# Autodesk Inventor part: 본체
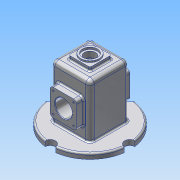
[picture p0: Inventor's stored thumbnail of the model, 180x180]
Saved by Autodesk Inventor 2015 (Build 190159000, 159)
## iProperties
Created: 2018-07
Part Number: 본체
Material: 알루미늄 6061
Document SubType Name: Modeling
Designer: user
Density: 2.7 g/cm^3
Appearance: 알루미늄 - 평지
Author: user
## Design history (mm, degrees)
sketch "스케치1"
  geometry: L1 (-37, -37)-(37, -37); L2 (37, -37)-(37, 37); L3 (37, 37)-(-37, 37); L4 (-37, 37)-(-37, -37); L5 (-37, -37)-(37, 37); L6 (37, -37)-(-37, 37); 1 further point
  constraints: 12 end point, 2 midpoint, 2 parallel, 1 horizontal, 1 perpendicular
  dimensions: "d0" = 74 distance of L3.end L2.end; "d1" = 74 distance of L2.end L1.end
extrude "돌출1" new body sketch "스케치1" stored distance "d2" = 100; taper "d3" = 0 deg
feature "쉘1" dims "d17" = 5
sketch "스케치4"
  geometry: L1 (32, 32)-(32, -32) reference; L2 (32, -32)-(-32, -32) reference; L3 (-32, -32)-(-32, 32) reference; L4 (-32, 32)-(32, 32) reference; C1 r 75 at (0, 0); 1 further point
  constraints: 1 centre point, 1 coincident
  dimensions: "d18" = 150 diameter of C1
extrude "돌출3" join sketch "스케치4" distance "d19" = 10; taper "d20" = 0 deg
sketch "스케치5"
  geometry: L1 (0, 0)-(-75, 0); 1 further point
  constraints: 2 end point, 1 coincident, 1 horizontal, 1 horizontal alignment, 1 other
hole "구멍2" sketch "스케치5" at (-75, 0) diameter "d21" = 20; stored, may be unused: countersink angle "d25" = 90 deg, drill point angle "d27" = 118 deg; dims "d22" = 6, "d23" = 4, "d24" = 2, "d26" = 8
sketch "스케치6"
  geometry: L1 (12, -80)-(62, -80); L2 (62, -80)-(62, -30); L3 (62, -30)-(12, -30); L4 (12, -30)-(12, -80); L5 (12, -80)-(62, -30); L6 (62, -80)-(12, -30); L7 (46.978, -110)-(27.022, -110) reference; 1 further point
  constraints: 12 end point, 2 midpoint, 2 parallel, 1 horizontal, 1 perpendicular
  dimensions: "d31" = 50 distance of L3.end L2.end; "d32" = 50 distance of L2.end L1.end; "d77" = 55 distance from line of L7 point (37, -55)
extrude "돌출4" join sketch "스케치6" distance "d33" = 13; taper "d34" = 0 deg
sketch "스케치9"
  geometry: L1 (-20, -20)-(20, -20); L2 (20, -20)-(20, 20); L3 (20, 20)-(-20, 20); L4 (-20, 20)-(-20, -20); L5 (-20, -20)-(20, 20); L6 (20, -20)-(-20, 20); 1 further point
  constraints: 12 end point, 2 midpoint, 2 parallel, 1 horizontal, 1 perpendicular
  dimensions: "d42" = 40 distance of L3.end L2.end; "d43" = 40 distance of L2.end L1.end
extrude "돌출6" join sketch "스케치9" distance "d44" = 7; taper "d45" = 0 deg
sketch "스케치10"
  geometry: C1 r 17.5 at (0, 0); 1 further point
  constraints: 1 centre point, 1 coincident
  dimensions: "d46" = 35 diameter of C1
extrude "돌출7" join sketch "스케치10" distance "d47" = 3; taper "d48" = 0 deg
sketch "스케치11"
  geometry: C1 r 17.5 at (0, 0) reference; 1 further point
  constraints: 1 coincident
hole "구멍3" sketch "스케치11" at (0, 0) diameter "d49" = 21; stored, may be unused: countersink angle "d53" = 90 deg, drill point angle "d55" = 118 deg; dims "d50" = 6, "d51" = 28, "d52" = 4, "d54" = 8
fillet "모깎기1" dims "d56" = 6
sketch "스케치13"
  geometry: A1 r 6 centre (18, -74) between (12, -74) and (18, -80) reference; A2 r 6 centre (56, -74) between (56, -80) and (62, -74) reference; A3 r 6 centre (56, -36) between (62, -36) and (56, -30) reference; A4 r 6 centre (18, -36) between (18, -30) and (12, -36) reference; 4 further points
  constraints: 4 coincident
hole "구멍4" sketch "스케치13" at (18, -36), (18, -74), (56, -74), (56, -36) diameter "d57" = 3.242; stored, may be unused: countersink angle "d61" = 90 deg, drill point angle "d63" = 118 deg; dims "d58" = 8, "d59" = 28, "d60" = 4, "d62" = 10
fillet "모깎기2" dims "d64" = 3
fillet "모깎기3" dims "d65" = 8
fillet "모깎기4" dims "d66" = 8
fillet "모깎기5" dims "d67" = 3
fillet "모깎기6" dims "d68" = 3
fillet "모깎기7" dims "d69" = 3
fillet "모깎기8" dims "d70" = 3
fillet "모깎기9" dims "d74" = 3
sketch "스케치14"
  geometry: L1 (46.5, 18)-(11.5, 18) reference; L2 (66, -89)-(66, 0) reference; 2 further points
  constraints: 1 other
  dimensions: "d75" = 30 distance from line of point (29, -12) L1; "d76" = 37 distance from line of L2 point (29, -12)
sketch "스케치15"
  geometry: L1 (56, 14)-(56, 10.5) reference; L2 (56, 10.5)-(45, 10.5) reference; L3 (45, 10.5)-(45, 29) reference; L4 (42, 32)-(-60, 32) reference; L5 (-60, 32)-(-60, 65) reference; L6 (-60, 65)-(-50, 65) reference; L7 (-50, 65)-(-50, 40) reference; L8 (-47, 37)-(-33, 37) reference; L9 (-30, 40)-(-30, 50) reference; L10 (-30, 50)-(20, 50) reference; L11 (20, 50)-(20, 40) reference; L12 (23, 37)-(42, 37) reference; L13 (50, 29)-(50, 23) reference; L14 (53, 20)-(57, 20) reference; L15 (57, 20)-(57, 17.5) reference; L16 (57, 17.5)-(60, 17.5) reference; L17 (60, 17.5)-(60, 14) reference; L18 (60, 14)-(56, 14) reference; L19 (56, -10.5)-(56, -14) reference; L20 (56, -14)-(60, -14) reference; L21 (60, -14)-(60, -17.5) reference; L22 (60, -17.5)-(57, -17.5) reference; L23 (57, -17.5)-(57, -20) reference; L24 (57, -20)-(53, -20) reference; L25 (50, -23)-(50, -29) reference; L26 (42, -37)-(23, -37) reference; L27 (20, -40)-(20, -50) reference; L28 (20, -50)-(-30, -50) reference; L29 (-30, -50)-(-30, -40) reference; L30 (-33, -37)-(-47, -37) reference; L31 (-50, -40)-(-50, -65) reference; L32 (-50, -65)-(-60, -65) reference; L33 (-60, -65)-(-60, -32) reference; L34 (-60, -32)-(42, -32) reference; L35 (45, -29)-(45, -10.5) reference; L36 (45, -10.5)-(56, -10.5) reference; L37 (-5, 50)-(-5, 0); L38 (-60, -29)-(-60, 29) reference; L39 (20, 32)-(17.452, 25); L40 (17.452, 25)-(-5, 25); L41 (20, 32)-(-5, 32); A1 r 3 centre (42, 29) between (45, 29) and (42, 32) reference; A2 r 3 centre (-47, 40) between (-50, 40) and (-47, 37) reference; A3 r 3 centre (-33, 40) between (-33, 37) and (-30, 40) reference; A4 r 3 centre (23, 40) between (20, 40) and (23, 37) reference; A5 r 8 centre (42, 29) between (50, 29) and (42, 37) reference; A6 r 3 centre (53, 23) between (50, 23) and (53, 20) reference; A7 r 3 centre (53, -23) between (53, -20) and (50, -23) reference; A8 r 8 centre (42, -29) between (42, -37) and (50, -29) reference; A9 r 3 centre (23, -40) between (23, -37) and (20, -40) reference; A10 r 3 centre (-33, -40) between (-30, -40) and (-33, -37) reference; A11 r 3 centre (-47, -40) between (-47, -37) and (-50, -40) reference; A12 r 3 centre (42, -29) between (42, -32) and (45, -29) reference; 1 further point
  constraints: 8 end point, 3 point on line, 2 midpoint, 1 perpendicular, 1 vertical
  dimensions: "d78" = 5 distance between parallel lines of L4 L12 (derived); "d79" = 55 distance between parallel lines of L38 L37 (derived); "d80" = 50 diameter of L39.start L37; "d81" = 110 deg angle of L4 L39; "d82" = 7 distance between parallel lines of L40 L41
revolve "회전2" sketch "스케치15" stored, may be unused: angle "d83" = 90 deg
sketch "스케치16"
  geometry: L1 (56, -30)-(18, -30) reference; L2 (12, -36)-(12, -74) reference; C1 r 16 at (37, -55); 3 further points
  constraints: 2 midpoint, 1 centre point, 1 horizontal alignment, 1 vertical alignment
  dimensions: "d84" = 32 diameter of C1
extrude "돌출8" cut sketch "스케치16" stored distance "d85" = 3; taper "d86" = 0 deg
chamfer "모따기2" distance "d87" = 1; stored, may be unused: second distance "d88" = 2, angle "d89" = 45 deg
feature "엠보싱1" dims "d0" = 74, "d1" = 74, "d90" = 0.5, "d91" = 0
node "솔리드1"
pattern_circular "원형 패턴2" dims angle "d29" = 360 deg
mirror "대칭1"
mirror "대칭2"
mirror "대칭3"
node "절단 모서리 투영2"
